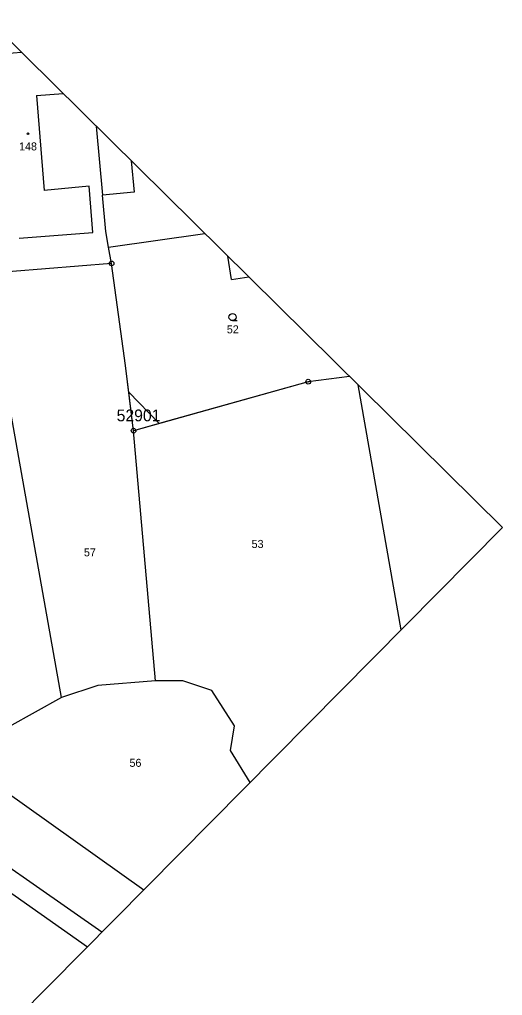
# Model space of a CAD drawing. Extents: x -777175 to -776673, y -1110537 to -1110036.
# Drawn here: x -776775.4 to -776672.9, y -1110431.1 to -1110223.9 of the extents above; entities that cross this region are included whole.
import ezdxf

# ---------------------------------------------------------------- set-up
doc = ezdxf.new("R2010")
doc.units = 0
for name, color, linetype in [('BPEJ', 7, 'Continuous'), ('Katastr_HRANICE DRÁHY', 7, 'Continuous'), ('Katastr_Hranice parcel', 7, 'Continuous'), ('Katastr_Parcelní čísla', 7, 'Continuous'), ('Katastr_Slučkované čáry', 7, 'Continuous'), ('Katastr_Značky kultur', 7, 'Continuous')]:
    doc.layers.add(name, color=color, linetype=linetype)

msp = doc.modelspace()

# ---------------------------------------------------------------- linework, layer by layer
at = {"layer": 'BPEJ'}
for points in [[(-776752.19, -1110303.01), (-776752.89, -1110297.34), (-776755.83, -1110275.7), (-776776.85, -1110277.4), (-776780.63, -1110277.66)], [(-776705.36, -1110299.69), (-776714.14, -1110300.8), (-776745.76, -1110309.67)], [(-776745.76, -1110309.67), (-776751.19, -1110311.2), (-776752.19, -1110303.01)], [(-776752.19, -1110303.01), (-776745.76, -1110309.67)]]:
    msp.add_lwpolyline(points, dxfattribs=at)
at = {"layer": 'Defpoints'}
for p, q in [((-776672.94, -1110331.74), (-776971.6, -1110036.44)), ((-776876.14, -1110537.25), (-776672.94, -1110331.74))]:
    msp.add_line(p, q, dxfattribs=at)
at = {"layer": 'Katastr_HRANICE DRÁHY'}
for points in [[(-776757.91, -1110417.68), (-776792.98, -1110393.16), (-776846.61, -1110355.09), (-776904.52, -1110315.47), (-776922.51, -1110314.75), (-776940.41, -1110317.34)], [(-776849.62, -1110338.22), (-776813.64, -1110363.55), (-776795.25, -1110376.34), (-776788.84, -1110380.33), (-776748.99, -1110408.66)]]:
    msp.add_lwpolyline(points, dxfattribs=at)
at = {"layer": 'Katastr_Hranice parcel'}
msp.add_line((-776766.43, -1110367.83), (-776782.5, -1110277.79), dxfattribs=at)
for points in [[(-776778.51, -1110231.13), (-776774.98, -1110230.85)], [(-776759.09, -1110246.56), (-776757.74, -1110261.17)], [(-776757.04, -1110268.94), (-776757.74, -1110261.17)], [(-776756.46, -1110272.21), (-776757.04, -1110268.94)], [(-776756.46, -1110272.21), (-776736.03, -1110269.37)], [(-776755.83, -1110275.7), (-776756.46, -1110272.21)], [(-776730.4, -1110279.14), (-776731.19, -1110274.15)], [(-776755.83, -1110275.7), (-776776.85, -1110277.4)], [(-776752.89, -1110297.34), (-776755.83, -1110275.7)], [(-776730.4, -1110279.14), (-776726.73, -1110278.56)], [(-776751.19, -1110311.2), (-776752.89, -1110297.34)], [(-776705.36, -1110299.69), (-776714.14, -1110300.8)], [(-776714.14, -1110300.8), (-776751.19, -1110311.2)], [(-776694.41, -1110353.46), (-776703.54, -1110301.49)], [(-776726.46, -1110385.87), (-776730.62, -1110379.11), (-776729.8, -1110373.88), (-776734.55, -1110366.33), (-776740.71, -1110364.29), (-776746.53, -1110364.29), (-776751.19, -1110311.2)], [(-776848.72, -1110358.87), (-776760.96, -1110420.76)], [(-776746.53, -1110364.29), (-776758.73, -1110365.29), (-776766.43, -1110367.83), (-776788.84, -1110380.33)]]:
    msp.add_lwpolyline(points, dxfattribs=at)
at = {"layer": 'Katastr_Slučkované čáry'}
for points in [[(-776771.77, -1110240.07), (-776766.11, -1110239.62)], [(-776771.77, -1110240.07), (-776770.17, -1110260.2)], [(-776751.69, -1110253.88), (-776751.07, -1110260.55)], [(-776760.58, -1110259.26), (-776770.17, -1110260.2)], [(-776759.81, -1110269.15), (-776760.58, -1110259.26)], [(-776751.07, -1110260.55), (-776757.74, -1110261.17)], [(-776775.44, -1110270.36), (-776759.81, -1110269.15)]]:
    msp.add_lwpolyline(points, dxfattribs=at)
at = {"layer": 'Katastr_Značky kultur'}
for p, q in [((-776755.88, -1110275.7), (-776755.78, -1110275.7)), ((-776730.19, -1110287.84), (-776729.19, -1110287.84)), ((-776714.19, -1110300.8), (-776714.09, -1110300.8)), ((-776751.24, -1110311.2), (-776751.14, -1110311.2))]:
    msp.add_line(p, q, dxfattribs=at)
for centre, radius in [((-776773.57, -1110248.17), 0.175), ((-776755.83, -1110275.7), 0.499), ((-776730.19, -1110287.09), 0.75), ((-776714.14, -1110300.8), 0.499), ((-776751.19, -1110311.2), 0.499)]:
    msp.add_circle(centre, radius, dxfattribs=at)

# ---------------------------------------------------------------- texts
at = {"layer": 'BPEJ'}
msp.add_text('52901', height=2.5, dxfattribs=at).set_placement((-776754.77, -1110309.21))
at = {"layer": 'Katastr_Parcelní čísla'}
for s, p in [('148', (-776775.46, -1110251.7)), ('52', (-776731.4, -1110290.54)), ('53', (-776726.14, -1110336.1)), ('57', (-776761.7, -1110337.88)), ('56', (-776752.04, -1110382.57))]:
    msp.add_text(s, height=1.7, dxfattribs=at).set_placement(p)

doc.saveas('drawing.dxf')
